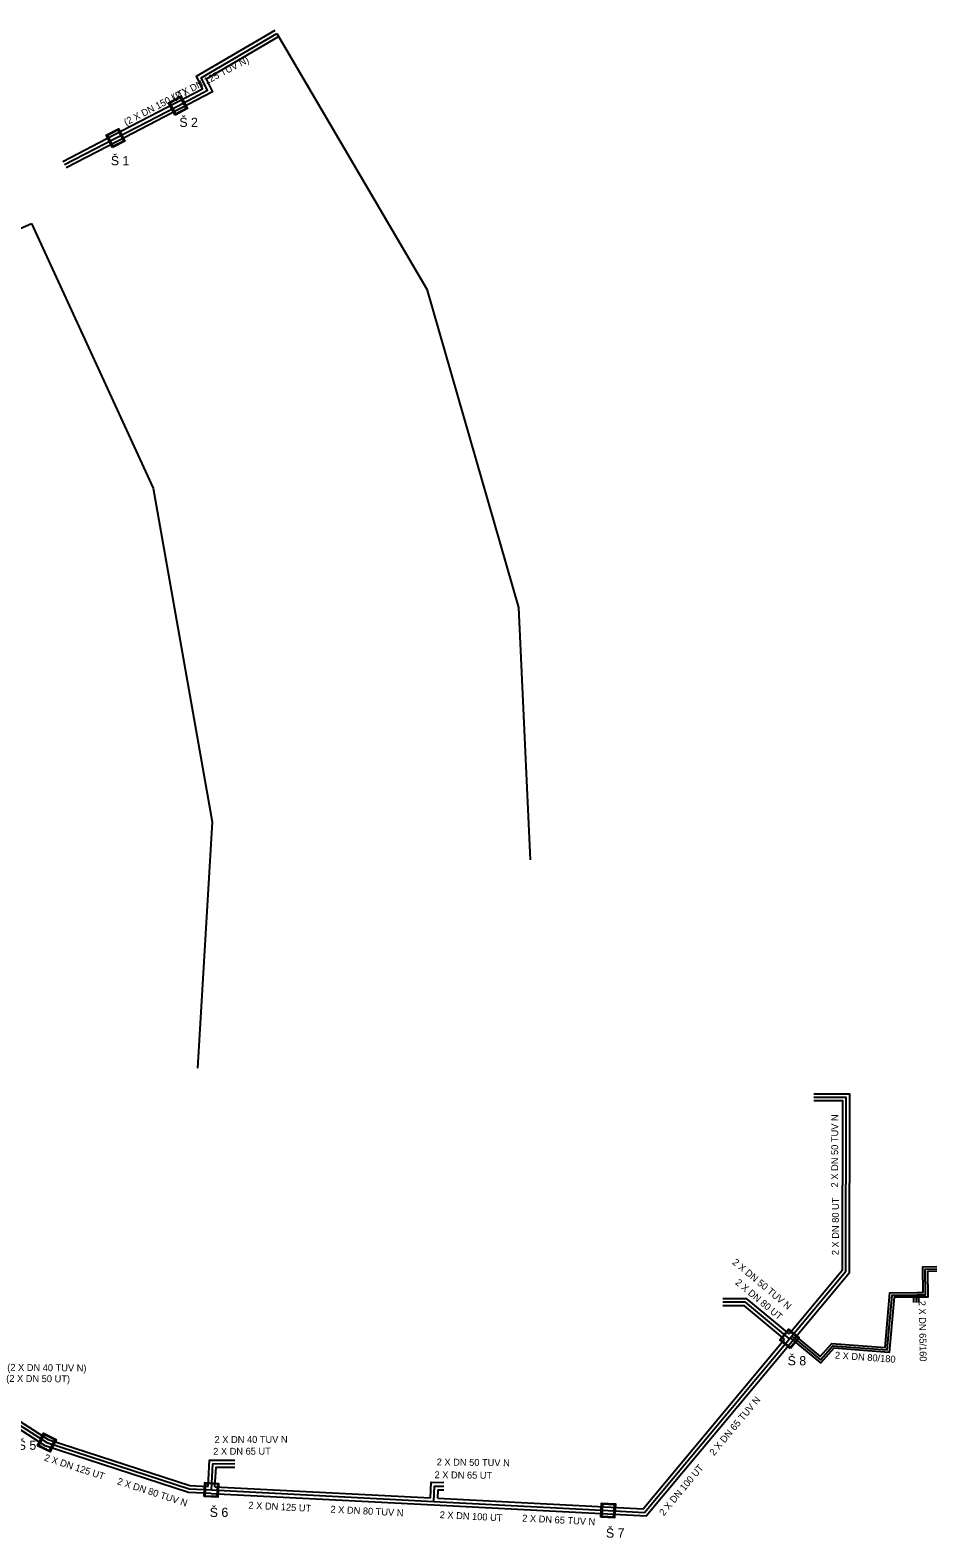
# Model space of a CAD drawing. Extents: x -606118 to -604472, y -1157869 to -1156854.
# Drawn here: x -605176.4 to -604980, y -1157868.6 to -1157542 of the extents above; entities that cross this region are included whole.
import ezdxf

# ---------------------------------------------------------------- set-up
doc = ezdxf.new("R2010")
doc.units = 0
for name, color, linetype in [('Osa trasy teplovodu', 7, 'Continuous'), ('označení šachty', 7, 'Continuous'), ('Teplovod - trasa - okraj', 7, 'Continuous'), ('Teplovod - trasa popis', 7, 'Continuous'), ('Teplovod - trasa popis 2', 7, 'Continuous'), ('Šachta trasy teplovodu', 7, 'Continuous')]:
    doc.layers.add(name, color=color, linetype=linetype)

msp = doc.modelspace()

# ---------------------------------------------------------------- linework, layer by layer
at = {"layer": 'Osa trasy teplovodu'}
for p, q in [((-604984.49, -1157815.95), (-604984.45, -1157817.6)), ((-605137.17, -1157858.23), (-605088.96, -1157860.73))]:
    msp.add_line(p, q, dxfattribs=at)
for points in [[(-605168.99, -1157571.13), (-605157.93, -1157565.39), (-605144.39, -1157558.36), (-605137.99, -1157555.03), (-605139.37, -1157552.31), (-605122.98, -1157542.69)], [(-605122.98, -1157542.69), (-605090.46, -1157598.11), (-605070.65, -1157667.08), (-605068.07, -1157721.76)], [(-605180.76, -1157581.88), (-605179.24, -1157585.24), (-605176.16, -1157583.85)], [(-605176.16, -1157583.85), (-605149.79, -1157641.2), (-605137.02, -1157713.5), (-605140.14, -1157766.88)], [(-605011.92, -1157825.5), (-604999.68, -1157810.83), (-604999.61, -1157773.22), (-605006.61, -1157773.21)], [(-604984.29, -1157815.97), (-604982.42, -1157815.96), (-604982.49, -1157810.37), (-604979.99, -1157810.35)], [(-605011.41, -1157824.89), (-605005.2, -1157830.02), (-605002.52, -1157826.99), (-604990.76, -1157827.89), (-604989.7, -1157816), (-604984.29, -1157815.97)], [(-605011.92, -1157825.5), (-605021.41, -1157817.57), (-605026.38, -1157817.56)], [(-605088.96, -1157860.73), (-605051.22, -1157862.68), (-605043.3, -1157863.09), (-605011.92, -1157825.5)], [(-605184.1, -1157840.78), (-605172.81, -1157847.96), (-605172.81, -1157847.96), (-605141.95, -1157858.01), (-605137.17, -1157858.23)], [(-605137.17, -1157858.23), (-605136.87, -1157852.54), (-605132.05, -1157852.53)], [(-605088.96, -1157860.73), (-605088.79, -1157857.38), (-605086.79, -1157857.4)]]:
    msp.add_lwpolyline(points, dxfattribs=at)
at = {"layer": 'Teplovod - trasa - okraj'}
for p, q in [((-604984.95, -1157817.61), (-604984.99, -1157815.96)), ((-604983.99, -1157815.94), (-604983.95, -1157817.59)), ((-605136.38, -1157857.52), (-605089.72, -1157859.94)), ((-605137.2, -1157858.98), (-605089, -1157861.48))]:
    msp.add_line(p, q, dxfattribs=at)
for points in [[(-605169.36, -1157570.42), (-605158.29, -1157564.67), (-605144.76, -1157557.65), (-605139.06, -1157554.69), (-605140.42, -1157552), (-605123.38, -1157542)], [(-605122.57, -1157543.38), (-605138.31, -1157552.62), (-605136.92, -1157555.38), (-605144.02, -1157559.07), (-605157.56, -1157566.1), (-605168.62, -1157571.84)], [(-605122.98, -1157542.69), (-605090.46, -1157598.11), (-605070.65, -1157667.08), (-605068.07, -1157721.76)], [(-605176.16, -1157583.85), (-605149.79, -1157641.2), (-605137.02, -1157713.5), (-605140.14, -1157766.88)], [(-605011.34, -1157825.98), (-604998.93, -1157811.11), (-604998.86, -1157772.47), (-605006.61, -1157772.46)], [(-605012.02, -1157824.44), (-605000.43, -1157810.56), (-605000.37, -1157773.97), (-605006.62, -1157773.96)], [(-604984.29, -1157815.47), (-604982.93, -1157815.47), (-604982.93, -1157815.47), (-604983, -1157809.88), (-604980, -1157809.85)], [(-604979.99, -1157810.85), (-604981.99, -1157810.87), (-604981.92, -1157816.46), (-604984.29, -1157816.47)], [(-605011.1, -1157824.5), (-605005.26, -1157829.33), (-605005.26, -1157829.33), (-605002.73, -1157826.47), (-604991.21, -1157827.36), (-604990.15, -1157815.5), (-604984.29, -1157815.47)], [(-605012.02, -1157824.44), (-605021.14, -1157816.82), (-605026.38, -1157816.81)], [(-605012.98, -1157825.59), (-605021.69, -1157818.32), (-605026.38, -1157818.31)], [(-604984.29, -1157816.47), (-604989.24, -1157816.49), (-604990.3, -1157828.43), (-605002.31, -1157827.5), (-605005.15, -1157830.72), (-605011.73, -1157825.27)], [(-605088.12, -1157860.02), (-605043.64, -1157862.32), (-605012.98, -1157825.59)], [(-605089, -1157861.48), (-605042.97, -1157863.86), (-605011.34, -1157825.98)], [(-605137.2, -1157858.98), (-605142.09, -1157858.76), (-605173.14, -1157848.64), (-605184.5, -1157841.41)], [(-605183.13, -1157840.51), (-605172.49, -1157847.27), (-605141.82, -1157857.27), (-605137.87, -1157857.45)], [(-605137.87, -1157857.45), (-605137.58, -1157851.8), (-605132.05, -1157851.78)], [(-605136.38, -1157857.52), (-605136.16, -1157853.29), (-605132.05, -1157853.28)], [(-605089.72, -1157859.94), (-605089.55, -1157856.57), (-605086.78, -1157856.6)], [(-605088.12, -1157860.02), (-605088.03, -1157858.19), (-605086.8, -1157858.2)]]:
    msp.add_lwpolyline(points, dxfattribs=at)
at = {"layer": 'Šachta trasy teplovodu'}
for points in [[(-605145, -1157560.39), (-605146.43, -1157557.75), (-605143.78, -1157556.32), (-605142.35, -1157558.96), (-605145, -1157560.39)], [(-605142.61, -1157558.89), (-605143.86, -1157556.57), (-605146.17, -1157557.82), (-605144.92, -1157560.14), (-605142.61, -1157558.89)], [(-605158.57, -1157567.41), (-605159.95, -1157564.74), (-605157.29, -1157563.36), (-605155.9, -1157566.02), (-605158.57, -1157567.41)], [(-605156.15, -1157565.94), (-605157.37, -1157563.61), (-605159.7, -1157564.82), (-605158.49, -1157567.16), (-605156.15, -1157565.94)], [(-605011.73, -1157827.61), (-605014.04, -1157825.68), (-605012.11, -1157823.38), (-605009.81, -1157825.3), (-605011.73, -1157827.61)], [(-605010.07, -1157825.33), (-605012.09, -1157823.64), (-605013.77, -1157825.66), (-605011.76, -1157827.35), (-605010.07, -1157825.33)], [(-605174.82, -1157848.65), (-605173.5, -1157845.95), (-605170.8, -1157847.27), (-605172.12, -1157849.97), (-605174.82, -1157848.65)], [(-605172.21, -1157849.72), (-605171.05, -1157847.35), (-605173.41, -1157846.2), (-605174.57, -1157848.56), (-605172.21, -1157849.72)], [(-605138.74, -1157859.65), (-605138.59, -1157856.65), (-605135.59, -1157856.81), (-605135.74, -1157859.81), (-605138.74, -1157859.65)], [(-605135.92, -1157859.61), (-605135.78, -1157856.98), (-605138.41, -1157856.85), (-605138.55, -1157859.47), (-605135.92, -1157859.61)], [(-605052.8, -1157864.1), (-605052.64, -1157861.1), (-605049.64, -1157861.25), (-605049.8, -1157864.26), (-605052.8, -1157864.1)], [(-605049.98, -1157864.06), (-605049.84, -1157861.43), (-605052.46, -1157861.3), (-605052.6, -1157863.92), (-605049.98, -1157864.06)]]:
    msp.add_lwpolyline(points, dxfattribs=at)

# ---------------------------------------------------------------- texts
at = {"layer": 'označení šachty'}
for s, p in [('Š 2', (-605144.1, -1157562.96)), ('Š 1', (-605158.94, -1157571.27)), ('Š 8', (-605012.32, -1157831.23)), ('Š 5', (-605179.12, -1157849.53)), ('Š 6', (-605137.53, -1157864.08)), ('Š 7', (-605051.68, -1157868.57))]:
    msp.add_text(s, height=2, dxfattribs=at).set_placement(p)
at = {"layer": 'Teplovod - trasa popis'}
for s, rotation, p in [('(2 X DN 150 UT)', 27.4447, (-605155.64, -1157562.73)), ('2 X DN 80 UT', 89.8971, (-605001.23, -1157807.38)), ('2 X DN 80 UT', 320.1688, (-605023.8, -1157813.52)), ('2 X DN 65/160', 271, (-604983.92, -1157817.25)), ('2 X DN 80/180', 356, (-605002.11, -1157829.76)), ('(2 X DN 50 UT)', 359.4737, (-605181.62, -1157834.8)), ('2 X DN 125 UT', 341.9412, (-605173.5, -1157851.83)), ('2 X DN 65 UT', 0.2292, (-605136.77, -1157850.62)), ('2 X DN 65 UT', 359.3591, (-605088.82, -1157855.68)), ('2 X DN 100 UT', 50.1338, (-605039.15, -1157863.94)), ('2 X DN 125 UT', 357.01, (-605129.16, -1157862.26)), ('2 X DN 100 UT', 357.01, (-605087.73, -1157864.32))]:
    msp.add_text(s, height=1.5, rotation=rotation, dxfattribs=at).set_placement(p)
at = {"layer": 'Teplovod - trasa popis 2'}
for s, rotation, p in [('(2 X DN 125 TUV N)', 27.4447, (-605145.09, -1157557.34)), ('2 X DN 50 TUV N', 89.8971, (-605001.38, -1157792.69)), ('2 X DN 50 TUV N', 320.1688, (-605024.43, -1157809.14)), ('(2 X DN 40 TUV N)', 359.4737, (-605181.4, -1157832.41)), ('2 X DN 65 TUV N', 50.1338, (-605028.26, -1157850.91)), ('2 X DN 40 TUV N', 0.2292, (-605136.47, -1157848.07)), ('2 X DN 50 TUV N', 359.3591, (-605088.35, -1157852.92)), ('2 X DN 80 TUV N', 341.9412, (-605157.7, -1157856.96)), ('2 X DN 80 TUV N', 357.01, (-605111.39, -1157863.14)), ('2 X DN 65 TUV N', 357.01, (-605069.85, -1157865.06))]:
    msp.add_text(s, height=1.5, rotation=rotation, dxfattribs=at).set_placement(p)

doc.saveas('drawing.dxf')
